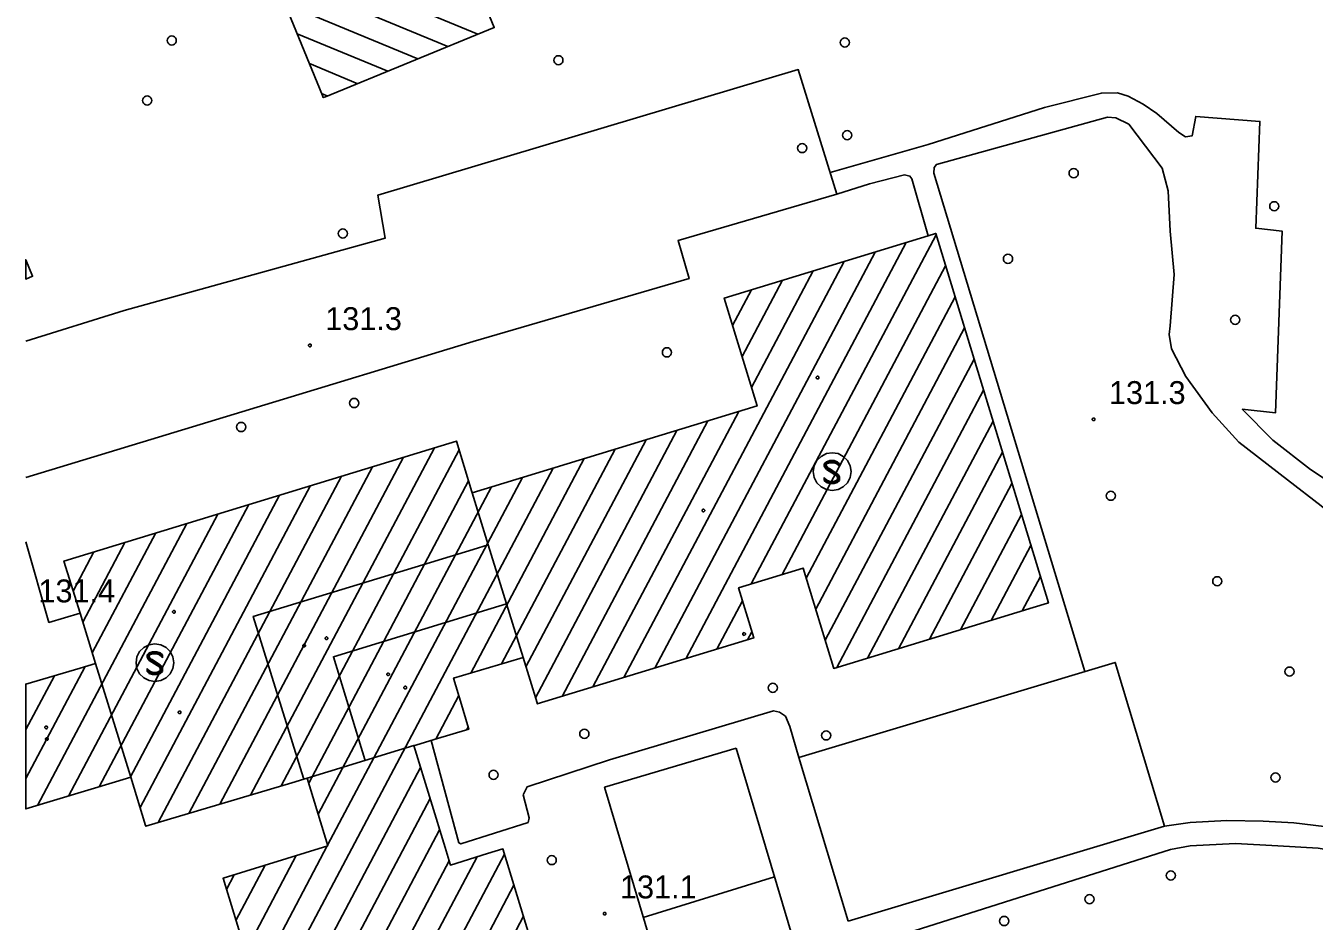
# Model space of a CAD drawing. Extents: x 513373 to 514978, y 5038576 to 5040180.
# Drawn here: x 513373 to 513457.4, y 5038719.9 to 5038778.5 of the extents above; entities that cross this region are included whole.
import ezdxf

# ---------------------------------------------------------------- set-up
doc = ezdxf.new("R2010")
doc.units = 0
for name, color, linetype in [('3010204', 7, 'Continuous'), ('3030201', 7, 'Continuous'), ('3060104', 7, 'Continuous'), ('C1131', 7, 'Continuous'), ('C12211', 7, 'Continuous'), ('C21195', 7, 'Continuous'), ('CAMP_C12211', 7, 'Continuous'), ('CAMP_C21195', 7, 'Continuous'), ('Default', 7, 'Continuous'), ('F12107', 7, 'Continuous'), ('F12131', 7, 'Continuous'), ('F12132', 7, 'Continuous'), ('G4315', 7, 'Continuous'), ('TOP920', 7, 'Continuous')]:
    doc.layers.add(name, color=color, linetype=linetype)

# ---------------------------------------------------------------- blocks, each defined once
blk = doc.blocks.new('CAMP_81469986')
at = {"layer": 'CAMP_C12211'}
for p, q in [((-1.641, 20.163), (-3.009, 20.729)), ((-0.838, 18.207), (-4.956, 19.912)), ((-0.035, 16.25), (-6.903, 19.095)), ((0.768, 14.294), (-8.851, 18.278)), ((1.571, 12.338), (-10.798, 17.461)), ((2.374, 10.382), (-12.746, 16.645)), ((3.177, 8.426), (-12.566, 14.947)), ((3.979, 6.47), (-11.765, 12.991)), ((4.782, 4.513), (-10.964, 11.036)), ((5.585, 2.557), (-10.163, 9.08)), ((6.388, 0.601), (-9.362, 7.125)), ((7.191, -1.355), (-8.561, 5.17)), ((7.994, -3.311), (-7.76, 3.214)), ((8.797, -5.267), (-6.959, 1.259)), ((9.6, -7.224), (-6.158, -0.696)), ((10.387, -9.173), (-5.356, -2.652)), ((11.184, -11.127), (-4.555, -4.608)), ((11.982, -13.081), (-3.754, -6.563)), ((12.779, -15.035), (-2.953, -8.518)), ((12.084, -16.371), (-2.152, -10.474)), ((10.118, -17.18), (-1.351, -12.429)), ((8.151, -17.989), (-0.549, -14.385)), ((6.185, -18.798), (0.252, -16.34)), ((4.218, -19.607), (1.053, -18.296)), ((2.252, -20.416), (1.854, -20.251))]:
    blk.add_line(p, q, dxfattribs=at)
blk = doc.blocks.new('CAMP_7295D72C')
at = {"layer": 'CAMP_C12211'}
for p, q in [((15.402, 5.835), (27.505, 28.695)), ((11.114, 0.944), (25.534, 28.177)), ((9.09, 0.327), (23.51, 27.56)), ((7.067, -0.29), (21.486, 26.943)), ((15.419, 18.691), (19.462, 26.326)), ((17.426, 6.452), (28.125, 26.661)), ((14.799, 20.725), (17.438, 25.71)), ((14.179, 22.76), (15.414, 25.093)), ((18.998, 6.217), (28.745, 24.626)), ((19.619, 4.183), (29.366, 22.592)), ((20.239, 2.149), (29.986, 20.557)), ((20.992, 0.365), (30.606, 18.523)), ((5.043, -0.907), (14.588, 17.121)), ((3.019, -1.524), (12.564, 16.504)), ((23.016, 0.982), (31.226, 16.488)), ((0.651, 0.415), (8.516, 15.27)), ((1.275, -1.612), (10.54, 15.887)), ((-17.372, -7.98), (-5.338, 14.749)), ((-15.356, -7.378), (-3.717, 14.606)), ((-0.945, 0.606), (6.492, 14.653)), ((25.04, 1.599), (31.846, 14.454)), ((-21.404, -9.183), (-9.388, 13.51)), ((-19.388, -8.582), (-7.363, 14.13)), ((-2.961, 0.006), (4.468, 14.036)), ((-23.42, -9.785), (-11.414, 12.891)), ((-16.459, -22.283), (2.444, 13.419)), ((-12.321, -11.262), (0.42, 12.802)), ((-24.597, -8.802), (-13.439, 12.272)), ((-13.562, -7.195), (-3.094, 12.575)), ((-12.941, -9.228), (-1.603, 12.185)), ((27.064, 2.216), (32.466, 12.419)), ((-27.268, -7.437), (-17.489, 11.033)), ((-25.249, -6.828), (-15.464, 11.652)), ((-29.288, -8.045), (-19.515, 10.413)), ((29.088, 2.833), (33.086, 10.385)), ((-31.307, -8.654), (-21.54, 9.794)), ((-28.349, 3.345), (-25.59, 8.555)), ((-27.723, 1.321), (-23.565, 9.175)), ((-28.974, 5.369), (-27.615, 7.936)), ((31.112, 3.45), (33.706, 8.35)), ((33.136, 4.067), (34.326, 6.316)), ((13.138, 1.561), (14.823, 4.742)), ((15.162, 2.178), (15.443, 2.708)), ((-32.079, -6.906), (-28.195, 0.43)), ((-32.079, -3.7), (-30.208, -0.167)), ((-5.249, -4.317), (-3.742, -1.471)), ((-3.237, -3.721), (-3.133, -3.526)), ((-15.838, -24.317), (-6.237, -6.182)), ((-15.218, -26.35), (-5.616, -8.215)), ((-14.597, -28.383), (-4.995, -10.248)), ((-17.08, -20.25), (-12.345, -11.308)), ((-18.322, -16.184), (-16.408, -12.569)), ((-17.701, -18.217), (-14.376, -11.939)), ((-13.976, -30.416), (-4.374, -12.281)), ((-12.474, -30.784), (-2.542, -12.026)), ((-10.448, -30.164), (-0.748, -11.844)), ((-18.943, -14.151), (-18.439, -13.2)), ((-8.422, -29.543), (-0.127, -13.877)), ((-6.396, -28.923), (0.494, -15.91)), ((-4.37, -28.302), (1.114, -17.943)), ((-2.345, -27.682), (1.735, -19.976)), ((-0.319, -27.061), (2.356, -22.009)), ((1.707, -26.441), (2.977, -24.043))]:
    blk.add_line(p, q, dxfattribs=at)
blk = doc.blocks.new('CAMP_C37EC05A')
at = {"layer": 'CAMP_C21195'}
blk.add_line((-0.043, -0.043), (0.043, 0.043), dxfattribs=at)
blk = doc.blocks.new('08020400')
at = {"layer": 'Default'}
for p, q in [((-0.086, 0.028), (-0.09, 0)), ((-0.09, 0), (-0.086, -0.028)), ((-0.073, 0.053), (-0.086, 0.028)), ((-0.053, 0.073), (-0.073, 0.053)), ((-0.028, 0.086), (-0.053, 0.073)), ((0, 0.09), (-0.028, 0.086)), ((0.028, 0.086), (0, 0.09)), ((0.053, 0.073), (0.028, 0.086)), ((0.073, 0.053), (0.053, 0.073)), ((0.086, 0.028), (0.073, 0.053)), ((0.09, 0), (0.086, 0.028)), ((0.086, -0.028), (0.09, 0)), ((-0.086, -0.028), (-0.073, -0.053)), ((-0.073, -0.053), (-0.053, -0.073)), ((-0.053, -0.073), (-0.028, -0.086)), ((-0.028, -0.086), (0, -0.09)), ((0, -0.09), (0.028, -0.086)), ((0.028, -0.086), (0.053, -0.073)), ((0.053, -0.073), (0.073, -0.053)), ((0.073, -0.053), (0.086, -0.028))]:
    blk.add_line(p, q, dxfattribs=at)
blk = doc.blocks.new('NSIMB25')
at = {"layer": 'Default'}
for p, q in [((-0.086, 0.028), (-0.09, 0)), ((-0.09, 0), (-0.086, -0.028)), ((-0.073, 0.053), (-0.086, 0.028)), ((-0.053, 0.073), (-0.073, 0.053)), ((-0.028, 0.086), (-0.053, 0.073)), ((0, 0.09), (-0.028, 0.086)), ((0.028, 0.086), (0, 0.09)), ((0.053, 0.073), (0.028, 0.086)), ((0.073, 0.053), (0.053, 0.073)), ((0.086, 0.028), (0.073, 0.053)), ((0.09, 0), (0.086, 0.028)), ((0.086, -0.028), (0.09, 0)), ((-0.086, -0.028), (-0.073, -0.053)), ((-0.073, -0.053), (-0.053, -0.073)), ((-0.053, -0.073), (-0.028, -0.086)), ((-0.028, -0.086), (0, -0.09)), ((0, -0.09), (0.028, -0.086)), ((0.028, -0.086), (0.053, -0.073)), ((0.053, -0.073), (0.073, -0.053)), ((0.073, -0.053), (0.086, -0.028))]:
    blk.add_line(p, q, dxfattribs=at)
blk = doc.blocks.new('05010100')
at = {"layer": 'Default'}
for p, q in [((-0.143, 0.046), (-0.15, 0)), ((-0.15, 0), (-0.143, -0.046)), ((-0.121, 0.088), (-0.143, 0.046)), ((-0.088, 0.121), (-0.121, 0.088)), ((-0.046, 0.143), (-0.088, 0.121)), ((0, 0.15), (-0.046, 0.143)), ((0.046, 0.143), (0, 0.15)), ((0.088, 0.121), (0.046, 0.143)), ((0.121, 0.088), (0.088, 0.121)), ((0.143, 0.046), (0.121, 0.088)), ((0.15, 0), (0.143, 0.046)), ((0.143, -0.046), (0.15, 0)), ((-0.143, -0.046), (-0.121, -0.088)), ((-0.121, -0.088), (-0.088, -0.121)), ((-0.088, -0.121), (-0.046, -0.143)), ((-0.046, -0.143), (0, -0.15)), ((0, -0.15), (0.046, -0.143)), ((0.046, -0.143), (0.088, -0.121)), ((0.088, -0.121), (0.121, -0.088)), ((0.121, -0.088), (0.143, -0.046))]:
    blk.add_line(p, q, dxfattribs=at)
blk = doc.blocks.new('03030201')
at = {"layer": 'Default'}
for p, q in [((-0.728, 1.001), (-1.001, 0.728)), ((-0.382, 1.177), (-0.728, 1.001)), ((0, 1.237), (-0.382, 1.177)), ((0.382, 1.177), (0, 1.237)), ((0.728, 1.001), (0.382, 1.177)), ((1.001, 0.728), (0.728, 1.001)), ((-1.177, 0.382), (-1.238, 0)), ((-1.238, 0), (-1.177, -0.382)), ((-1.001, 0.728), (-1.177, 0.382)), ((-0.518, 0.508), (-0.368, 0.643)), ((-0.518, 0.358), (-0.518, 0.508)), ((-0.443, 0.223), (-0.518, 0.358)), ((-0.333, 0.584), (-0.451, 0.478)), ((-0.451, 0.478), (-0.451, 0.376)), ((-0.451, 0.376), (-0.389, 0.265)), ((-0.368, 0.148), (-0.443, 0.223)), ((-0.389, 0.265), (-0.326, 0.201)), ((-0.298, 0.526), (-0.383, 0.448)), ((-0.383, 0.448), (-0.383, 0.394)), ((-0.383, 0.394), (-0.335, 0.306)), ((-0.368, 0.643), (-0.158, 0.718)), ((0.148, -0.186), (-0.368, 0.148)), ((-0.335, 0.306), (-0.287, 0.257)), ((-0.147, 0.651), (-0.333, 0.584)), ((-0.326, 0.201), (0.183, -0.128)), ((-0.135, 0.583), (-0.298, 0.526)), ((-0.287, 0.257), (-0.18, 0.198)), ((-0.18, 0.198), (0.337, -0.137)), ((-0.158, 0.718), (0.127, 0.718)), ((0.115, 0.651), (-0.147, 0.651)), ((0.103, 0.583), (-0.135, 0.583)), ((0.266, 0.526), (0.103, 0.583)), ((0.301, 0.584), (0.115, 0.651)), ((0.127, 0.718), (0.337, 0.643)), ((0.487, 0.327), (0.266, 0.526)), ((0.487, 0.418), (0.301, 0.584)), ((0.337, 0.643), (0.487, 0.508)), ((0.487, 0.508), (0.487, 0.327)), ((1.177, 0.382), (1.001, 0.728)), ((1.238, 0), (1.177, 0.382)), ((1.177, -0.382), (1.238, 0)), ((-1.177, -0.382), (-1.001, -0.728)), ((-1.001, -0.728), (-0.728, -1.001)), ((-0.518, -0.39), (-0.298, -0.588)), ((-0.518, -0.572), (-0.518, -0.39)), ((-0.333, -0.647), (-0.518, -0.481)), ((-0.368, -0.707), (-0.518, -0.572)), ((-0.158, -0.782), (-0.368, -0.707)), ((-0.147, -0.714), (-0.333, -0.647)), ((-0.298, -0.588), (-0.135, -0.647)), ((0.127, -0.782), (-0.158, -0.782)), ((0.115, -0.714), (-0.147, -0.714)), ((-0.135, -0.647), (0.103, -0.647)), ((0.103, -0.647), (0.266, -0.588)), ((0.301, -0.647), (0.115, -0.714)), ((0.337, -0.707), (0.127, -0.782)), ((0.254, -0.245), (0.148, -0.186)), ((0.183, -0.128), (0.295, -0.191)), ((0.302, -0.293), (0.254, -0.245)), ((0.266, -0.588), (0.352, -0.512)), ((0.295, -0.191), (0.357, -0.253)), ((0.419, -0.542), (0.301, -0.647)), ((0.352, -0.382), (0.302, -0.293)), ((0.337, -0.137), (0.412, -0.212)), ((0.487, -0.572), (0.337, -0.707)), ((0.352, -0.512), (0.352, -0.382)), ((0.357, -0.253), (0.419, -0.364)), ((0.412, -0.212), (0.487, -0.347)), ((0.419, -0.364), (0.419, -0.542)), ((0.487, -0.347), (0.487, -0.572)), ((0.728, -1.001), (1.001, -0.728)), ((1.001, -0.728), (1.177, -0.382)), ((-0.728, -1.001), (-0.382, -1.177)), ((-0.382, -1.177), (0, -1.238)), ((0, -1.238), (0.382, -1.177)), ((0.382, -1.177), (0.728, -1.001))]:
    blk.add_line(p, q, dxfattribs=at)
blk = doc.blocks.new('A$C3704598A')
at = {"layer": '3010204'}
for points in [[(-0.008, -622.291), (6.431, -620.288), (23.519, -615.535), (23.038, -612.72), (50.552, -604.509), (53.076, -612.657)], [(52.638, -611.243), (59.044, -609.406), (66.672, -606.996), (70.384, -606.047), (71.444, -606.04), (72.13, -606.249), (73.131, -606.783), (74.008, -607.389)], [(74.367, -610.967), (72.173, -608.073), (71.343, -607.665), (70.776, -607.631), (59.589, -610.721), (59.437, -610.915), (59.431, -611.285), (69.303, -643.902)], [(92.872, -651.548), (93.342, -648.667), (93.254, -645.665), (92.735, -643.42), (91.755, -639.917), (90.412, -636.949), (89.063, -634.787), (86.93, -632.574), (84.077, -630.692), (81.606, -628.767), (79.606, -626.735), (81.777, -626.976), (82.21, -615.083), (80.486, -614.89), (80.767, -607.902), (76.557, -607.577), (76.323, -608.852), (75.897, -608.916), (75.451, -608.621), (74.008, -607.389)], [(74.367, -610.967), (74.748, -612.446), (74.884, -615.091), (75.152, -617.916), (74.879, -621.275), (74.829, -621.857), (74.979, -622.777), (75.905, -624.599), (77.632, -626.965), (79.387, -628.884), (82.571, -631.352), (84.775, -633.072), (87.335, -635.154), (88.775, -637.137), (89.745, -639.072), (90.955, -641.837), (91.473, -644.351), (91.99, -646.864), (92.017, -649.038), (91.58, -651.262)], [(53.076, -612.657), (55.207, -611.978), (57.508, -611.401), (57.851, -611.48), (57.971, -611.655), (59.044, -615.395)], [(-0.008, -631.198), (29.263, -622.311), (43.4, -618.186), (42.678, -615.686), (53.076, -612.657)], [(3.546, -640.096), (1.51, -640.696), (-0.008, -635.413)], [(50.593, -649.524), (49.994, -647.507), (49.718, -646.83), (49.314, -646.559), (48.932, -646.481), (38.203, -649.684), (32.8, -651.441), (32.551, -651.965), (32.934, -653.483), (32.881, -653.794)], [(32.881, -653.794), (28.467, -655.183), (28.325, -655.109), (26.518, -648.416)], [(74.514, -654.017), (76.206, -653.794), (78.605, -653.657), (80.979, -653.698), (82.972, -653.804), (85.68, -654.14), (89.722, -654.969)], [(74.899, -655.556), (76.194, -655.318), (79.153, -655.162), (81.929, -655.319), (84.572, -655.475), (86.989, -655.853), (89.405, -656.404)], [(54.856, -666.757), (53.973, -663.461), (53.983, -662.845), (54.236, -662.431), (54.96, -661.876), (74.899, -655.556)]]:
    blk.add_lwpolyline(points, dxfattribs=at)
at = {"layer": '3060104'}
for points in [[(53.812, -660.237), (74.514, -654.017), (71.295, -643.304), (50.593, -649.524), (53.812, -660.237)], [(46.493, -648.911), (51.804, -666.759), (43.181, -669.324), (37.87, -651.477), (46.493, -648.911)], [(40.406, -660.001), (49, -657.337)]]:
    blk.add_lwpolyline(points, dxfattribs=at)
at = {"layer": 'C1131'}
for points in [[(27.66, -594.413), (27.668, -594.469), (27.683, -594.501), (27.69, -594.516), (30.647, -601.76), (19.607, -606.302), (19.463, -606.342), (19.407, -606.205), (12.513, -589.379), (10.683, -584.914), (10.57, -584.637), (9.106, -581.062), (7.387, -576.866), (7.321, -576.704), (4.315, -569.367), (14.503, -565.093), (15.101, -564.842), (15.461, -564.691), (15.468, -564.708), (15.581, -564.985), (18.389, -571.825), (18.502, -572.1), (27.581, -594.221)], [(66.922, -639.42), (66.857, -639.44), (65.92, -639.725), (52.871, -643.704), (52.852, -643.639), (50.869, -637.14), (49.867, -637.445), (46.638, -638.429), (47.637, -641.709), (33.47, -646.028), (33.451, -645.964), (32.534, -642.985), (31.453, -639.473), (30.264, -635.617), (29.213, -632.207), (47.857, -626.524), (45.704, -619.46), (58.55, -615.545), (59.044, -615.395), (59.534, -615.245), (59.553, -615.24)], [(-0.008, -616.954), (0.435, -618.041), (-0.008, -618.224), (-0.008, -616.953)], [(29.213, -632.207), (30.264, -635.617), (29.261, -635.922), (14.879, -640.297), (18.16, -650.888), (18.18, -650.951), (17.406, -651.182), (7.852, -654.034), (7.834, -653.976), (6.861, -650.827), (4.56, -643.378), (3.546, -640.096), (2.489, -636.676), (27.173, -629.127), (28.175, -628.82), (29.193, -632.143)], [(31.453, -639.473), (30.451, -639.78), (20.13, -642.938), (22.171, -649.663), (22.191, -649.727), (18.41, -650.882), (18.18, -650.951), (18.16, -650.888), (14.879, -640.297), (29.261, -635.922), (30.264, -635.617)], [(32.534, -642.985), (31.529, -643.284), (27.99, -644.339), (28.504, -646.072), (28.894, -647.391), (28.982, -647.688), (26.73, -648.354), (25.512, -648.715), (25.393, -648.75), (24.391, -649.056), (22.191, -649.727), (22.171, -649.663), (20.13, -642.938), (30.451, -639.78), (31.453, -639.473)], [(6.861, -650.827), (5.858, -651.129), (-0.009, -652.897), (-0.009, -644.731), (3.555, -643.675), (4.56, -643.378)], [(18.467, -675.14), (18.321, -675.169), (18.306, -675.118), (18.278, -675.026), (12.906, -657.436), (19.76, -655.307), (18.41, -650.882), (22.191, -649.727), (24.391, -649.056), (25.393, -648.75), (26.501, -652.377), (27.429, -655.415), (27.762, -656.505), (27.781, -656.57), (30.219, -655.825), (31.22, -655.519), (35.608, -669.89)]]:
    blk.add_lwpolyline(points, close=True, dxfattribs=at)
at = {"layer": 'C12211'}
blk.add_lwpolyline([(27.66, -594.413), (27.668, -594.469), (27.683, -594.501), (27.69, -594.516), (30.647, -601.76), (19.607, -606.302), (19.463, -606.342), (19.407, -606.205), (12.513, -589.379), (10.683, -584.914), (10.57, -584.637), (9.106, -581.062), (7.387, -576.866), (7.321, -576.704), (4.315, -569.367), (14.503, -565.093), (15.101, -564.842), (15.461, -564.691), (15.468, -564.708), (15.581, -564.985), (18.389, -571.825), (18.502, -572.1), (27.581, -594.221)], close=True, dxfattribs=at)
blk.add_lwpolyline([(18.278, -675.026), (12.906, -657.436), (19.76, -655.307), (18.41, -650.882), (18.18, -650.951), (17.406, -651.182), (7.852, -654.034), (7.834, -653.976), (6.861, -650.827), (5.858, -651.129), (-0.009, -652.897), (-0.009, -644.731), (3.555, -643.675), (4.56, -643.378), (3.546, -640.096), (2.489, -636.676), (27.173, -629.127), (28.175, -628.82), (29.193, -632.143), (29.213, -632.207), (47.857, -626.524), (45.704, -619.46), (58.55, -615.545), (59.044, -615.395), (59.534, -615.245), (59.553, -615.24), (66.922, -639.42), (66.857, -639.44), (65.92, -639.725), (52.871, -643.704), (52.852, -643.639), (50.869, -637.14), (49.867, -637.445), (46.638, -638.429), (47.637, -641.709), (33.47, -646.028), (33.451, -645.964), (32.534, -642.985), (31.529, -643.284), (27.99, -644.339), (28.504, -646.072), (28.894, -647.391), (28.982, -647.688), (26.73, -648.354), (25.512, -648.715), (25.393, -648.75), (26.501, -652.377), (27.429, -655.415), (27.762, -656.505), (27.781, -656.57), (30.219, -655.825), (31.22, -655.519), (35.608, -669.89)], dxfattribs=at)
at = {"layer": 'C21195'}
blk.add_lwpolyline([(-0.008, -616.954), (0.435, -618.041), (-0.008, -618.224), (-0.008, -616.953)], close=True, dxfattribs=at)
at = {"layer": '3030201'}
for p in [(52.768, -630.823), (8.444, -643.326)]:
    blk.add_blockref('03030201', p, dxfattribs=at)
at = {"layer": 'CAMP_C12211'}
for name, p in [('CAMP_81469986', (17.501, -585.827)), ('CAMP_7295D72C', (32.07, -644.01))]:
    blk.add_blockref(name, p, dxfattribs=at)
at = {"layer": 'CAMP_C21195'}
blk.add_blockref('CAMP_C37EC05A', (0.035, -617.209), dxfattribs=at)
at = {"layer": 'F12107'}
for p in [(18.589, -622.563), (69.88, -627.401), (37.878, -659.753)]:
    blk.add_blockref('08020400', p, dxfattribs=at)
at = {"layer": 'F12131'}
for p in [(51.813, -624.669), (19.673, -641.729), (23.708, -644.088), (10.058, -646.576), (1.328, -647.562)]:
    blk.add_blockref('NSIMB25', p, dxfattribs=at)
at = {"layer": 'F12132'}
for p in [(44.34, -633.368), (9.686, -640), (47.002, -641.45), (18.212, -642.207), (24.83, -644.959), (1.372, -648.32)]:
    blk.add_blockref('NSIMB25', p, dxfattribs=at)
at = {"layer": 'G4315', "xscale": 2, "yscale": 2}
for p in [(9.542, -602.606), (53.592, -602.742), (34.849, -603.902), (7.936, -606.537), (53.745, -608.799), (50.804, -609.646), (68.571, -611.289), (81.703, -613.457), (20.74, -615.239), (64.274, -616.895), (79.141, -620.893), (41.954, -623.017), (21.483, -626.333), (14.088, -627.902), (71.001, -632.401), (77.972, -638), (82.703, -643.911), (48.881, -644.968), (36.549, -647.983), (52.378, -648.084), (30.608, -650.668), (81.78, -650.837), (34.412, -656.245), (74.933, -657.249), (69.612, -658.798), (64.02, -660.233)]:
    blk.add_blockref('05010100', p, dxfattribs=at)
at = {"layer": 'TOP920'}
for s, p in [('131.3', (19.589, -621.563)), ('131.3', (70.88, -626.401)), ('131.4', (0.82, -639.381)), ('131.1', (38.878, -658.753))]:
    blk.add_text(s, height=1.5, dxfattribs=at).set_placement(p)

msp = doc.modelspace()

# ---------------------------------------------------------------- block references
at = {"layer": 'Default'}
msp.add_blockref('A$C3704598A', (513373.046, 5039380.14), dxfattribs=at)

doc.saveas('drawing.dxf')
